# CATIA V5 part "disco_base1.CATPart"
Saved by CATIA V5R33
Part number: disco_base1
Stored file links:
  C:\Users\Ryzen5700u\Desktop\robot_cicloidale_singolo\Assieme_robot_cicloidale_singolo\disco_base1.CATPart

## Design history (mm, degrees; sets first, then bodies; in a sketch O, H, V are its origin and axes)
Set1
  Point1 "Point.1": stored without definition
Body1 "Solido1" (main body)
  Solid1: solid without history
